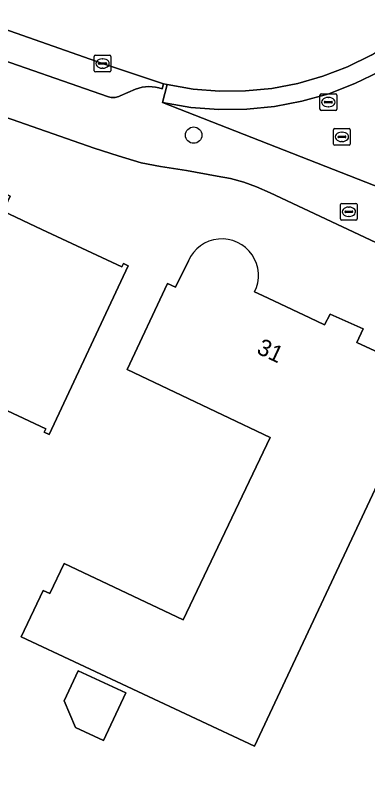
# Model space of a CAD drawing. Extents: x 158835 to 160077, y 386387 to 387778.
# Drawn here: x 159412.61 to 159433.67, y 386554.02 to 386600.05 of the extents above; entities that cross this region are included whole.
import ezdxf

# ---------------------------------------------------------------- set-up
doc = ezdxf.new("R2010")
doc.units = 0
for name, color, linetype in [('IMGEO_Boom', 7, 'Continuous'), ('IMGEO_Brandkraan', 7, 'Continuous'), ('IMGEO_Erf', 7, 'Continuous'), ('IMGEO_Kolk', 7, 'Continuous'), ('IMGEO_Pand', 7, 'Continuous'), ('IMGEO_Pand_nummerreeks', 7, 'Continuous'), ('IMGEO_Parkeervlak_open', 7, 'Continuous'), ('IMGEO_Rijbaan_lokaal_gesloten', 7, 'Continuous'), ('IMGEO_Rioolput', 7, 'Continuous'), ('IMGEO_Voetpad_open', 7, 'Continuous')]:
    doc.layers.add(name, color=color, linetype=linetype)

msp = doc.modelspace()

# ---------------------------------------------------------------- linework, layer by layer
at = {"layer": 'IMGEO_Boom'}
msp.add_circle((159423.269, 386592.883), 0.489, dxfattribs=at)
at = {"layer": 'IMGEO_Brandkraan'}
for p, q in [((159432.047, 386587.873), (159432.047, 386588.725)), ((159432.122, 386588.799), (159432.974, 386588.799)), ((159433.048, 386588.725), (159433.048, 386587.873)), ((159432.306, 386588.293), (159432.306, 386588.305)), ((159432.349, 386588.342), (159432.747, 386588.342)), ((159432.535, 386588.579), (159432.56, 386588.579)), ((159432.79, 386588.305), (159432.79, 386588.293)), ((159432.744, 386588.256), (159432.346, 386588.256)), ((159432.558, 386588.019), (159432.533, 386588.019)), ((159432.974, 386587.799), (159432.122, 386587.799))]:
    msp.add_line(p, q, dxfattribs=at)
for points in [[(159432.047, 386587.873), (159432.047, 386588.725)], [(159432.122, 386588.799), (159432.974, 386588.799)], [(159433.048, 386588.725), (159433.048, 386587.873)], [(159432.974, 386587.799), (159432.122, 386587.799)]]:
    msp.add_lwpolyline(points, dxfattribs=at)
for centre, radius, start, end in [((159432.124, 386588.723), 0.0765, 91.552, 178.448), ((159432.124, 386588.723), 0.0765, 91.552, 178.448), ((159432.972, 386588.723), 0.0765, 1.552, 88.448), ((159432.972, 386588.723), 0.0765, 1.552, 88.448), ((159432.346, 386588.302), 0.0403, 85.8775, 175.7526), ((159432.343, 386588.292), 0.0366, 178.938, 274.7102), ((159432.747, 386588.299), 0.043, 264.8664, 352.4533), ((159432.751, 386588.304), 0.0386, 1.7309, 96.639), ((159432.124, 386587.875), 0.0765, 181.552, 268.448), ((159432.124, 386587.875), 0.0765, 181.552, 268.448), ((159432.972, 386587.875), 0.0765, 271.552, 358.448), ((159432.972, 386587.875), 0.0765, 271.552, 358.448)]:
    msp.add_arc(centre, radius, start, end, dxfattribs=at)
for centre, major_axis, ratio, start_param, end_param in [((159432.534, 386588.299), (-0.387, 0.002), 0.722429, 4.712389, 7.853982), ((159432.559, 386588.299), (-0.39, 0.002), 0.717154, 1.570796, 4.712389)]:
    msp.add_ellipse(centre, major_axis=major_axis, ratio=ratio, start_param=start_param, end_param=end_param, dxfattribs=at)
at = {"layer": 'IMGEO_Erf'}
for points in [[(159426.262, 386590.078), (159425.471, 386590.29), (159424.673, 386590.43), (159422.846, 386590.766), (159421.294, 386591.006), (159420.138, 386591.222), (159418.758, 386591.64), (159417.314, 386592.1), (159409.486, 386594.837), (159405.916, 386596.132), (159403.97, 386596.822), (159400.475, 386598.135), (159386.22, 386603.858), (159382.649, 386605.402), (159367.084, 386612.517), (159363.661, 386614.16), (159351.051, 386620.582), (159347.709, 386622.366), (159334.021, 386630.024), (159330.778, 386632.045), (159325.211, 386635.435), (159320.616, 386638.324)], [(159427.775, 386521.258), (159463.884, 386569.807), (159463.112, 386572.777), (159443.151, 386582.231), (159434.161, 386586.457), (159427.852, 386589.423), (159427.031, 386589.796), (159426.262, 386590.078)], [(159415.531, 386567.253), (159422.639, 386563.873), (159427.834, 386574.797), (159419.285, 386578.862), (159421.698, 386584.015), (159422.191, 386583.79), (159422.95, 386585.363)], [(159426.916, 386583.501), (159427.382, 386583.283), (159430.211, 386581.959), (159431.101, 386581.542), (159431.423, 386582.175), (159433.397, 386581.294), (159433.035, 386580.479), (159437.29, 386578.493), (159435.176, 386573.963), (159426.904, 386556.32), (159412.961, 386562.87), (159414.279, 386565.642), (159414.675, 386565.453), (159415.531, 386567.253)]]:
    msp.add_lwpolyline(points, dxfattribs=at)
for points in [[(159404.331, 386590.559), (159407.577, 386589.029), (159408.074, 386590.108), (159408.922, 386589.723), (159409.349, 386590.627), (159412.303, 386589.232), (159411.884, 386588.326), (159414.183, 386587.246), (159418.976, 386584.995), (159419.077, 386585.202), (159419.362, 386585.063), (159414.623, 386574.97), (159414.334, 386575.106), (159414.427, 386575.305), (159403.837, 386580.282), (159403.204, 386578.934), (159399.641, 386580.609)], [(159415.523, 386559.032), (159416.371, 386560.839), (159419.209, 386559.506), (159417.869, 386556.654), (159416.207, 386557.435)]]:
    msp.add_lwpolyline(points, close=True, dxfattribs=at)
msp.add_arc((159424.957, 386584.482), 2.191, 333.395, 156.3058, dxfattribs=at)
at = {"layer": 'IMGEO_Kolk'}
for p, q in [((159417.32, 386596.739), (159417.32, 386597.591)), ((159417.395, 386597.665), (159418.247, 386597.665)), ((159418.321, 386597.591), (159418.321, 386596.739)), ((159417.579, 386597.159), (159417.579, 386597.171)), ((159418.017, 386597.122), (159417.619, 386597.122)), ((159417.622, 386597.208), (159418.02, 386597.208)), ((159417.808, 386597.445), (159417.833, 386597.445)), ((159418.063, 386597.171), (159418.063, 386597.159)), ((159418.247, 386596.665), (159417.395, 386596.665)), ((159417.831, 386596.885), (159417.806, 386596.885))]:
    msp.add_line(p, q, dxfattribs=at)
for points in [[(159417.32, 386596.739), (159417.32, 386597.591)], [(159417.395, 386597.665), (159418.247, 386597.665)], [(159418.321, 386597.591), (159418.321, 386596.739)], [(159418.247, 386596.665), (159417.395, 386596.665)]]:
    msp.add_lwpolyline(points, dxfattribs=at)
for centre, radius, start, end in [((159417.397, 386597.589), 0.0765, 91.552, 178.448), ((159417.397, 386597.589), 0.0765, 91.552, 178.448), ((159418.245, 386597.589), 0.0765, 1.552, 88.448), ((159418.245, 386597.589), 0.0765, 1.552, 88.448), ((159417.619, 386597.168), 0.0403, 85.8775, 175.7526), ((159417.616, 386597.158), 0.0366, 178.938, 274.7102), ((159418.02, 386597.165), 0.043, 264.8664, 352.4533), ((159418.024, 386597.17), 0.0386, 1.7309, 96.639), ((159417.397, 386596.741), 0.0765, 181.552, 268.448), ((159417.397, 386596.741), 0.0765, 181.552, 268.448), ((159418.245, 386596.741), 0.0765, 271.552, 358.448), ((159418.245, 386596.741), 0.0765, 271.552, 358.448)]:
    msp.add_arc(centre, radius, start, end, dxfattribs=at)
for centre, major_axis, ratio, start_param, end_param in [((159417.807, 386597.165), (-0.387, 0.002), 0.722429, 4.712389, 7.853982), ((159417.832, 386597.165), (-0.39, 0.002), 0.717154, 1.570796, 4.712389)]:
    msp.add_ellipse(centre, major_axis=major_axis, ratio=ratio, start_param=start_param, end_param=end_param, dxfattribs=at)
at = {"layer": 'IMGEO_Pand'}
for points in [[(159414.183, 386587.246), (159411.884, 386588.326), (159412.303, 386589.232), (159409.349, 386590.627), (159408.922, 386589.723), (159408.074, 386590.108), (159407.577, 386589.029), (159404.331, 386590.559), (159399.641, 386580.609), (159403.204, 386578.934), (159403.837, 386580.282), (159414.427, 386575.305), (159414.334, 386575.106), (159414.623, 386574.97), (159419.362, 386585.063), (159419.077, 386585.202), (159418.976, 386584.995)], [(159415.523, 386559.032), (159416.207, 386557.435), (159417.869, 386556.654), (159419.209, 386559.506), (159416.371, 386560.839)]]:
    msp.add_lwpolyline(points, close=True, dxfattribs=at)
msp.add_lwpolyline([(159422.95, 386585.363), (159422.191, 386583.79), (159421.698, 386584.015), (159419.285, 386578.862), (159427.834, 386574.797), (159422.639, 386563.873), (159415.531, 386567.253), (159414.675, 386565.453), (159414.279, 386565.642), (159412.961, 386562.87), (159426.904, 386556.32), (159435.176, 386573.963), (159437.29, 386578.493), (159433.035, 386580.479), (159433.397, 386581.294), (159431.423, 386582.175), (159431.101, 386581.542), (159430.211, 386581.959), (159427.382, 386583.283), (159426.916, 386583.501)], dxfattribs=at)
msp.add_arc((159424.957, 386584.482), 2.191, 333.395, 156.3058, dxfattribs=at)
at = {"layer": 'IMGEO_Parkeervlak_open'}
msp.add_lwpolyline([(159410.54, 386597.836), (159418.111, 386595.198), (159418.184, 386595.171), (159418.26, 386595.151), (159418.337, 386595.138), (159418.415, 386595.131), (159418.493, 386595.132), (159418.571, 386595.139), (159418.648, 386595.154), (159418.723, 386595.175), (159418.796, 386595.203), (159418.871, 386595.24), (159419.796, 386595.638), (159419.983, 386595.701), (159420.18, 386595.748), (159420.38, 386595.778), (159420.582, 386595.789), (159420.785, 386595.782), (159420.986, 386595.758), (159421.184, 386595.715), (159421.377, 386595.655), (159421.467, 386595.944), (159417.822, 386597.165), (159411.164, 386599.499)], dxfattribs=at)
at = {"layer": 'IMGEO_Rijbaan_lokaal_gesloten'}
msp.add_lwpolyline([(159411.164, 386599.499), (159417.822, 386597.165), (159421.467, 386595.944), (159421.688, 386595.906), (159423.238, 386595.64), (159424.806, 386595.514), (159426.378, 386595.529), (159427.943, 386595.684), (159429.488, 386595.978), (159431.001, 386596.409), (159432.469, 386596.973), (159433.881, 386597.666), (159435.225, 386598.483), (159436.49, 386599.416), (159437.668, 386600.459)], dxfattribs=at)
at = {"layer": 'IMGEO_Rioolput'}
for p, q in [((159430.821, 386594.433), (159430.821, 386595.285)), ((159430.896, 386595.359), (159431.748, 386595.359)), ((159431.822, 386595.285), (159431.822, 386594.433)), ((159431.08, 386594.853), (159431.08, 386594.865)), ((159431.518, 386594.816), (159431.12, 386594.816)), ((159431.123, 386594.902), (159431.521, 386594.902)), ((159431.309, 386595.139), (159431.334, 386595.139)), ((159431.564, 386594.865), (159431.564, 386594.853)), ((159431.748, 386594.359), (159430.896, 386594.359)), ((159431.332, 386594.579), (159431.307, 386594.579)), ((159431.631, 386592.353), (159431.631, 386593.205)), ((159431.706, 386593.279), (159432.558, 386593.279)), ((159432.119, 386593.059), (159432.144, 386593.059)), ((159432.632, 386593.205), (159432.632, 386592.353)), ((159431.89, 386592.773), (159431.89, 386592.785)), ((159432.328, 386592.736), (159431.93, 386592.736)), ((159431.933, 386592.822), (159432.331, 386592.822)), ((159432.142, 386592.499), (159432.117, 386592.499)), ((159432.374, 386592.785), (159432.374, 386592.773)), ((159432.558, 386592.279), (159431.706, 386592.279))]:
    msp.add_line(p, q, dxfattribs=at)
for points in [[(159430.821, 386594.433), (159430.821, 386595.285)], [(159430.896, 386595.359), (159431.748, 386595.359)], [(159431.822, 386595.285), (159431.822, 386594.433)], [(159431.748, 386594.359), (159430.896, 386594.359)], [(159431.631, 386592.353), (159431.631, 386593.205)], [(159431.706, 386593.279), (159432.558, 386593.279)], [(159432.632, 386593.205), (159432.632, 386592.353)], [(159432.558, 386592.279), (159431.706, 386592.279)]]:
    msp.add_lwpolyline(points, dxfattribs=at)
for centre, radius, start, end in [((159430.898, 386595.283), 0.0765, 91.552, 178.448), ((159430.898, 386595.283), 0.0765, 91.552, 178.448), ((159431.746, 386595.283), 0.0765, 1.552, 88.448), ((159431.746, 386595.283), 0.0765, 1.552, 88.448), ((159431.12, 386594.862), 0.0403, 85.8775, 175.7526), ((159431.117, 386594.852), 0.0366, 178.938, 274.7102), ((159431.521, 386594.859), 0.043, 264.8664, 352.4533), ((159431.525, 386594.864), 0.0386, 1.7309, 96.639), ((159430.898, 386594.435), 0.0765, 181.552, 268.448), ((159430.898, 386594.435), 0.0765, 181.552, 268.448), ((159431.746, 386594.435), 0.0765, 271.552, 358.448), ((159431.746, 386594.435), 0.0765, 271.552, 358.448), ((159431.708, 386593.203), 0.0765, 91.552, 178.448), ((159431.708, 386593.203), 0.0765, 91.552, 178.448), ((159432.556, 386593.203), 0.0765, 1.552, 88.448), ((159432.556, 386593.203), 0.0765, 1.552, 88.448), ((159431.93, 386592.782), 0.0403, 85.8775, 175.7526), ((159431.927, 386592.772), 0.0366, 178.938, 274.7102), ((159432.331, 386592.779), 0.043, 264.8664, 352.4533), ((159432.335, 386592.784), 0.0386, 1.7309, 96.639), ((159431.708, 386592.355), 0.0765, 181.552, 268.448), ((159431.708, 386592.355), 0.0765, 181.552, 268.448), ((159432.556, 386592.355), 0.0765, 271.552, 358.448), ((159432.556, 386592.355), 0.0765, 271.552, 358.448)]:
    msp.add_arc(centre, radius, start, end, dxfattribs=at)
for centre, major_axis, ratio, start_param, end_param in [((159431.308, 386594.859), (-0.387, 0.002), 0.722429, 4.712389, 7.853982), ((159431.333, 386594.859), (-0.39, 0.002), 0.717154, 1.570796, 4.712389), ((159432.118, 386592.779), (-0.387, 0.002), 0.722429, 4.712389, 7.853982), ((159432.143, 386592.779), (-0.39, 0.002), 0.717154, 1.570796, 4.712389)]:
    msp.add_ellipse(centre, major_axis=major_axis, ratio=ratio, start_param=start_param, end_param=end_param, dxfattribs=at)
at = {"layer": 'IMGEO_Voetpad_open'}
for points in [[(159351.051, 386620.582), (159363.661, 386614.16), (159367.084, 386612.517), (159382.649, 386605.402), (159386.22, 386603.858), (159400.475, 386598.135), (159403.97, 386596.822), (159405.916, 386596.132), (159409.486, 386594.837), (159417.314, 386592.1), (159418.758, 386591.64), (159420.138, 386591.222), (159421.294, 386591.006), (159422.846, 386590.766), (159424.673, 386590.43), (159425.471, 386590.29), (159426.262, 386590.078), (159427.031, 386589.796), (159427.852, 386589.423), (159434.161, 386586.457), (159443.151, 386582.231), (159463.112, 386572.777), (159468.116, 386570.333)], [(159442.679, 386598.473), (159438.488, 386599.716), (159437.182, 386598.56), (159435.838, 386597.569), (159434.41, 386596.7), (159432.909, 386595.964), (159431.35, 386595.365), (159429.742, 386594.907), (159428.1, 386594.594), (159426.438, 386594.43), (159424.767, 386594.414), (159423.101, 386594.547), (159421.41, 386594.838), (159435.489, 386589.322), (159437.663, 386593.877), (159438.232, 386593.602), (159441.275, 386592.153)], [(159435.489, 386589.322), (159421.41, 386594.838), (159421.688, 386595.906), (159421.467, 386595.944), (159421.377, 386595.655), (159421.184, 386595.715), (159420.986, 386595.758), (159420.785, 386595.782), (159420.582, 386595.789), (159420.38, 386595.778), (159420.18, 386595.748), (159419.983, 386595.701), (159419.796, 386595.638), (159418.871, 386595.24), (159418.796, 386595.203), (159418.723, 386595.175), (159418.648, 386595.154), (159418.571, 386595.139), (159418.493, 386595.132), (159418.415, 386595.131), (159418.337, 386595.138), (159418.26, 386595.151), (159418.184, 386595.171), (159418.111, 386595.198), (159410.54, 386597.836)], [(159433.881, 386597.666), (159432.469, 386596.973), (159431.001, 386596.409), (159429.488, 386595.978), (159427.943, 386595.684), (159426.378, 386595.529), (159424.806, 386595.514), (159423.238, 386595.64), (159421.688, 386595.906), (159421.41, 386594.838), (159423.101, 386594.547), (159424.767, 386594.414), (159426.438, 386594.43), (159428.1, 386594.594), (159429.742, 386594.907), (159431.35, 386595.365), (159432.909, 386595.964), (159434.41, 386596.7)]]:
    msp.add_lwpolyline(points, dxfattribs=at)

# ---------------------------------------------------------------- texts
at = {"layer": 'IMGEO_Pand_nummerreeks'}
msp.add_text('31', height=1, rotation=334.9157, dxfattribs=at).set_placement((159426.972, 386579.853))

doc.saveas('drawing.dxf')
